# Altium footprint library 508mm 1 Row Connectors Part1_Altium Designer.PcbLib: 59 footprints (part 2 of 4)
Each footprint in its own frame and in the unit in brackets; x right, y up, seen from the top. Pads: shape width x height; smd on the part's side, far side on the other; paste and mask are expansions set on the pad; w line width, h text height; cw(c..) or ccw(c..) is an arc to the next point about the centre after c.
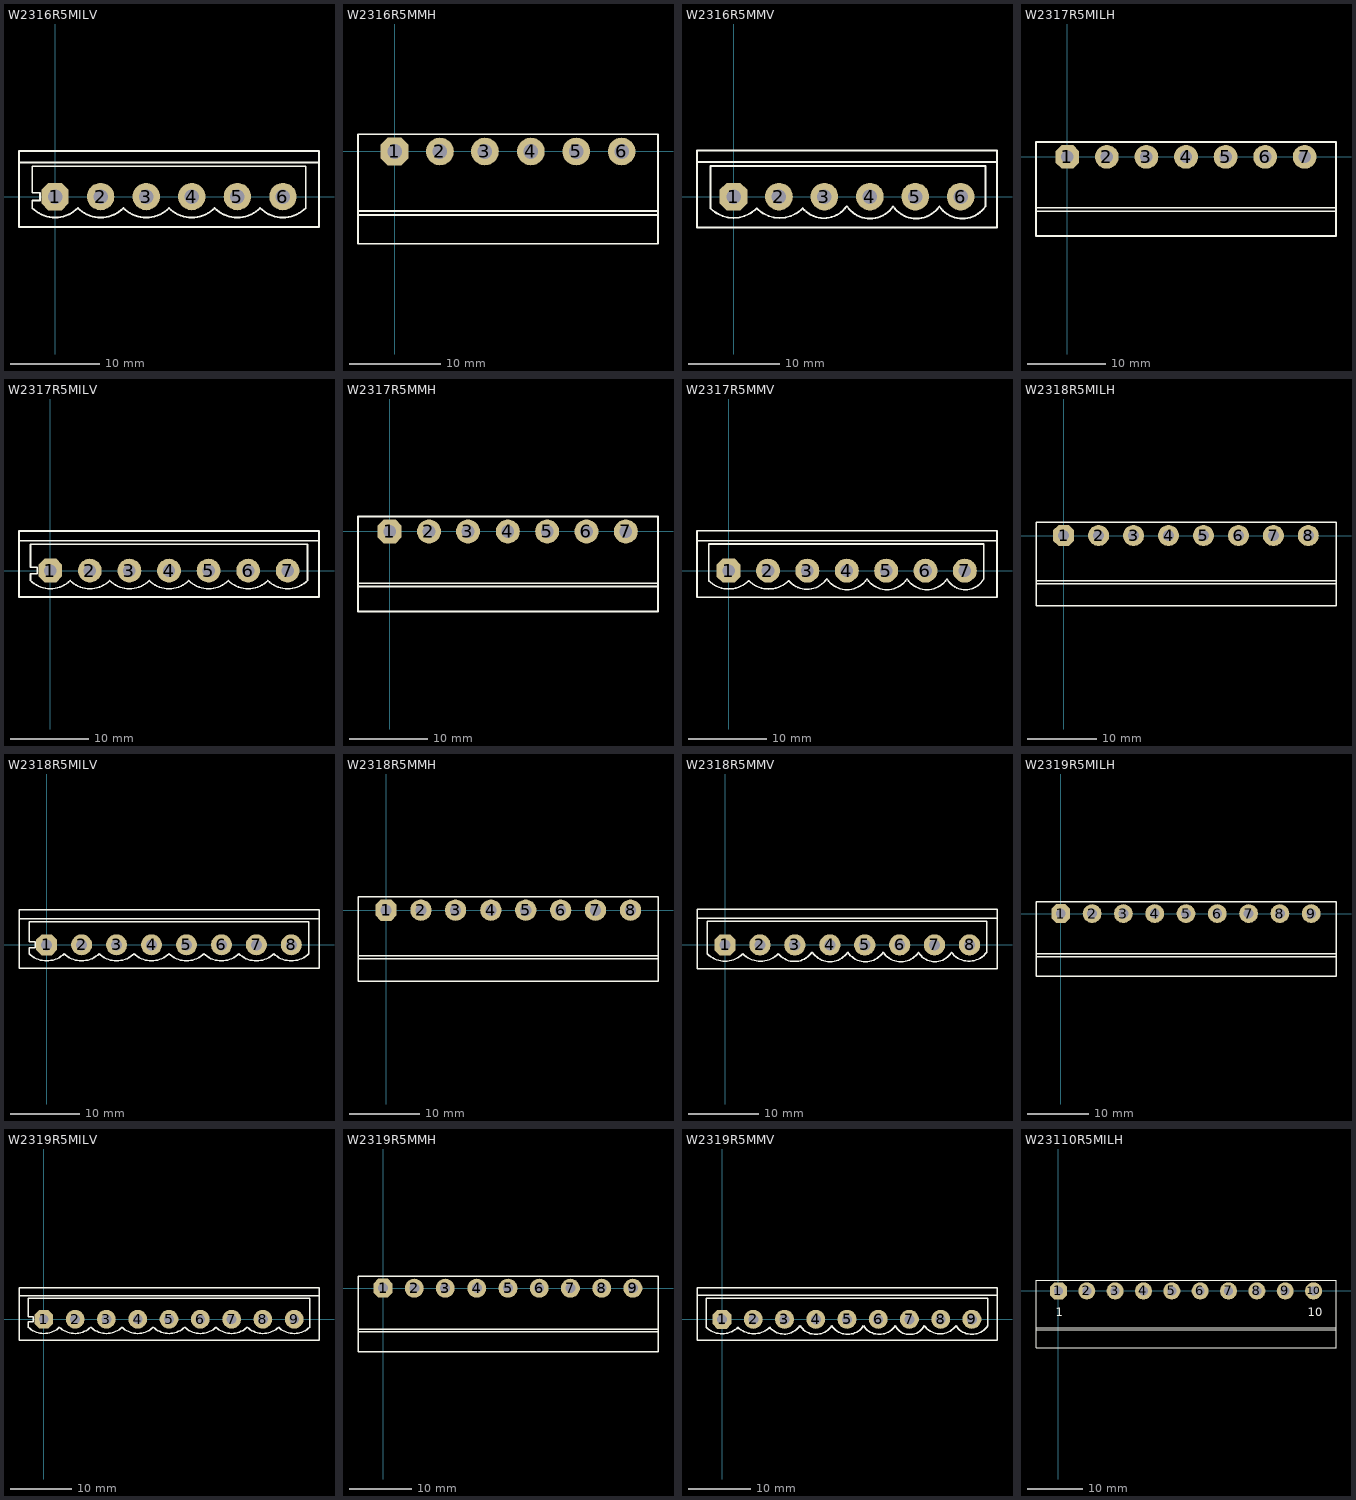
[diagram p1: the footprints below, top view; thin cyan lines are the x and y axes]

## W2316R5MILV [mil] "M.Hariri (Altium Designer)"
pads (6):
  oct 120x120 hole 62.99: 1(0,0)
  round 120 hole 62.99: 2(200,0) 3(400,0) 4(600,0) 5(800,0) 6(1000,0)
Top Overlay:
  lines w8: -158.33,150 1158.33,150 ; -100.17,-50.17 ccw(c0,50) 100.17,-50.17 ; -100,-50 -100,-16.67 -66.67,-16.67 -66.67,16.67 -100,16.67 -100,133.33 1100,133.33 1100,-50 ; 99.83,-50.17 ccw(c200,50) 300.17,-50.17 ; 299.83,-50.17 ccw(c400,50) 500.17,-50.17 ; 499.83,-50.17 ccw(c600,50) 700.17,-50.17 ; 699.83,-50.17 ccw(c800,50) 900.17,-50.17 ; 899.83,-50.17 ccw(c1000,50) 1100.17,-50.17 ; -158.33,-133.33 1158.33,-133.33 1158.33,200 -158.33,200 -158.33,-133.33

## W2316R5MMH [mil] "M.Hariri (Altium Designer)"
pads (6):
  oct 120x120 hole 62.99: 1(0,0)
  round 120 hole 62.99: 2(196.67,0) 3(391.67,0) 4(590.83,0) 5(787.5,0) 6(984.17,0)
Top Overlay:
  lines w8: -158.33,-275 1141.67,-275 ; -158.33,-258.33 1141.67,-258.33 ; -158.33,-400 -158.33,75 1141.67,75 1141.67,-400 -158.33,-400

## W2316R5MMV [mil] "M.Hariri (Altium Designer)"
pads (6):
  oct 120x120 hole 62.99: 1(0,0)
  round 120 hole 62.99: 2(196.67,0) 3(393.33,0) 4(590.83,0) 5(787.5,0) 6(984.17,0)
Top Overlay:
  lines w8: -158.33,150 1141.67,150 ; -100.17,-50.17 ccw(c0,50) 100.17,-50.17 ; -100,-50 -100,133.33 1091.67,133.33 1091.67,-41.67 ; 99.83,-50.17 ccw(c200,50) 300.17,-50.17 ; 299.7,-49.47 ccw(c391.67,25) 489.77,-41.17 ; 492.18,-42.1 ccw(c591.67,25) 691.15,-42.1 ; 692.18,-42.1 ccw(c791.67,25) 891.15,-42.1 ; 892.18,-42.1 ccw(c991.67,25) 1091.15,-42.1 ; -158.33,-133.33 1141.67,-133.33 1141.67,200 -158.33,200 -158.33,-133.33

## W2317R5MILH [mil] "M.Hariri (Altium Designer)"
pads (7):
  oct 120x120 hole 62.99: 1(0,0)
  round 120 hole 62.99: 2(200,0) 3(400,0) 4(600,0) 5(800,0) 6(1000,0) 7(1200,0)
Top Overlay:
  lines w8: -158.33,-275 1358.33,-275 ; -158.33,-258.33 1358.33,-258.33 ; -158.33,-400 -158.33,75 1358.33,75 1358.33,-400 -158.33,-400

## W2317R5MILV [mil] "M.Hariri (Altium Designer)"
pads (7):
  oct 120x120 hole 62.99: 1(0,0)
  round 120 hole 62.99: 2(200,0) 3(400,0) 4(600,0) 5(800,0) 6(1000,0) 7(1200,0)
Top Overlay:
  lines w8: -158.33,150 1358.33,150 ; -100.17,-50.17 ccw(c0,50) 100.17,-50.17 ; -100,-50 -100,-16.67 -66.67,-16.67 -66.67,16.67 -100,16.67 -100,133.33 1300,133.33 1300,-50 ; 99.83,-50.17 ccw(c200,50) 300.17,-50.17 ; 299.83,-50.17 ccw(c400,50) 500.17,-50.17 ; 499.83,-50.17 ccw(c600,50) 700.17,-50.17 ; 699.83,-50.17 ccw(c800,50) 900.17,-50.17 ; 899.83,-50.17 ccw(c1000,50) 1100.17,-50.17 ; 1099.83,-50.17 ccw(c1200,50) 1300.17,-50.17 ; -158.33,-133.33 1358.33,-133.33 1358.33,200 -158.33,200 -158.33,-133.33

## W2317R5MMH [mil] "M.Hariri (Altium Designer)"
pads (7):
  oct 120x120 hole 62.99: 1(0,0)
  round 120 hole 62.99: 2(196.67,0) 3(391.67,0) 4(590.83,0) 5(787.5,0) 6(984.17,0) 7(1180.83,0)
Top Overlay:
  lines w8: -158.33,-275 1341.67,-275 ; -158.33,-258.33 1341.67,-258.33 ; -158.33,-400 1341.67,-400 1341.67,75 -158.33,75 -158.33,-400

## W2317R5MMV [mil] "M.Hariri (Altium Designer)"
pads (7):
  oct 120x120 hole 62.99: 1(0,0)
  round 120 hole 62.99: 2(196.67,0) 3(393.33,0) 4(590.83,0) 5(787.5,0) 6(984.17,0) 7(1180.83,0)
Top Overlay:
  lines w8: -158.33,150 1341.67,150 ; -100.17,-50.17 ccw(c0,50) 100.17,-50.17 ; -100,-50 -100,133.33 1275,133.33 1275,-41.67 ; 99.83,-50.17 ccw(c200,50) 300.17,-50.17 ; 299.7,-49.47 ccw(c391.67,25) 489.77,-41.17 ; 492.18,-42.1 ccw(c591.67,25) 691.15,-42.1 ; 692.18,-42.1 ccw(c791.67,25) 891.15,-42.1 ; 892.18,-42.1 ccw(c991.67,25) 1091.15,-42.1 ; 1092.23,-42.17 ccw(c1183.33,8.33) 1274.44,-42.17 ; -158.33,-133.33 1341.67,-133.33 1341.67,200 -158.33,200 -158.33,-133.33

## W2318R5MILH [mil] "M.Hariri (Altium Designer)"
pads (8):
  oct 120x120 hole 62.99: 1(0,0)
  round 120 hole 62.99: 2(200,0) 3(400,0) 4(600,0) 5(800,0) 6(1000,0) 7(1200,0) 8(1400,0)
Top Overlay:
  lines w8: -158.33,-275 1558.33,-275 ; -158.33,-258.33 1558.33,-258.33 ; -158.33,-400 -158.33,75 1558.33,75 1558.33,-400 -158.33,-400

## W2318R5MILV [mil] "M.Hariri (Altium Designer)"
pads (8):
  oct 120x120 hole 62.99: 1(0,0)
  round 120 hole 62.99: 2(200,0) 3(400,0) 4(600,0) 5(800,0) 6(1000,0) 7(1200,0) 8(1400,0)
Top Overlay:
  lines w8: -158.33,150 1558.33,150 ; -100.17,-50.17 ccw(c0,50) 100.17,-50.17 ; -100,-50 -100,-16.67 -66.67,-16.67 -66.67,16.67 -100,16.67 -100,133.33 1500,133.33 1500,-50 ; 99.83,-50.17 ccw(c200,50) 300.17,-50.17 ; 299.83,-50.17 ccw(c400,50) 500.17,-50.17 ; 499.83,-50.17 ccw(c600,50) 700.17,-50.17 ; 699.83,-50.17 ccw(c800,50) 900.17,-50.17 ; 899.83,-50.17 ccw(c1000,50) 1100.17,-50.17 ; 1099.83,-50.17 ccw(c1200,50) 1300.17,-50.17 ; 1299.83,-50.17 ccw(c1400,50) 1500.17,-50.17 ; -158.33,-133.33 1558.33,-133.33 1558.33,200 -158.33,200 -158.33,-133.33

## W2318R5MMH [mil] "M.Hariri (Altium Designer)"
pads (8):
  oct 120x120 hole 62.99: 1(0,0)
  round 120 hole 62.99: 2(196.67,0) 3(391.67,0) 4(590.83,0) 5(787.5,0) 6(984.17,0) 7(1180.83,0) 8(1378.33,0)
Top Overlay:
  lines w8: -158.33,-275 1533.33,-275 ; -158.33,-258.33 1533.33,-258.33 ; -158.33,-400 -158.33,75 1533.33,75 1533.33,-400 -158.33,-400

## W2318R5MMV [mil] "M.Hariri (Altium Designer)"
pads (8):
  oct 120x120 hole 62.99: 1(0,0)
  round 120 hole 62.99: 2(196.67,0) 3(393.33,0) 4(590.83,0) 5(787.5,0) 6(984.17,0) 7(1180.83,0) 8(1378.33,0)
Top Overlay:
  lines w8: -158.33,150 1533.33,150 ; -100.17,-50.17 ccw(c0,50) 100.17,-50.17 ; -100,-50 -100,133.33 1475,133.33 1475,-41.67 ; 99.83,-50.17 ccw(c200,50) 300.17,-50.17 ; 299.7,-49.47 ccw(c391.67,25) 489.77,-41.17 ; 492.18,-42.1 ccw(c591.67,25) 691.15,-42.1 ; 692.18,-42.1 ccw(c791.67,25) 891.15,-42.1 ; 892.18,-42.1 ccw(c991.67,25) 1091.15,-42.1 ; 1092.23,-42.17 ccw(c1183.33,8.33) 1274.44,-42.17 ; 1275.17,-41.89 ccw(c1375,33.33) 1474.83,-41.89 ; -158.33,-133.33 1533.33,-133.33 1533.33,200 -158.33,200 -158.33,-133.33

## W2319R5MILH [mil] "M.Hariri (Altium Designer)"
pads (9):
  oct 120x120 hole 62.99: 1(0,0)
  round 120 hole 62.99: 2(200,0) 3(400,0) 4(600,0) 5(800,0) 6(1000,0) 7(1200,0) 8(1400,0) 9(1600,0)
Top Overlay:
  lines w8: -158.33,-275 1758.33,-275 ; -158.33,-258.33 1758.33,-258.33 ; -158.33,-400 1758.33,-400 1758.33,75 -158.33,75 -158.33,-400

## W2319R5MILV [mil] "M.Hariri (Altium Designer)"
pads (9):
  oct 120x120 hole 62.99: 1(0,0)
  round 120 hole 62.99: 2(200,0) 3(400,0) 4(600,0) 5(800,0) 6(1000,0) 7(1200,0) 8(1400,0) 9(1600,0)
Top Overlay:
  lines w8: -158.33,150 1758.33,150 ; -100.17,-50.17 ccw(c0,50) 100.17,-50.17 ; -100,-50 -100,-16.67 -66.67,-16.67 -66.67,16.67 -100,16.67 -100,133.33 1700,133.33 1700,-50 ; 99.83,-50.17 ccw(c200,50) 300.17,-50.17 ; 299.83,-50.17 ccw(c400,50) 500.17,-50.17 ; 499.83,-50.17 ccw(c600,50) 700.17,-50.17 ; 699.83,-50.17 ccw(c800,50) 900.17,-50.17 ; 899.83,-50.17 ccw(c1000,50) 1100.17,-50.17 ; 1099.83,-50.17 ccw(c1200,50) 1300.17,-50.17 ; 1299.83,-50.17 ccw(c1400,50) 1500.17,-50.17 ; 1499.83,-50.17 ccw(c1600,50) 1700.17,-50.17 ; -158.33,-133.33 1758.33,-133.33 1758.33,200 -158.33,200 -158.33,-133.33

## W2319R5MMH [mil] "M.Hariri (Altium Designer)"
pads (9):
  oct 120x120 hole 62.99: 1(0,0)
  round 120 hole 62.99: 2(196.67,0) 3(391.67,0) 4(590.83,0) 5(787.5,0) 6(984.17,0) 7(1180.83,0) 8(1378.33,0) 9(1575,0)
Top Overlay:
  lines w8: -158.33,-275 1733.33,-275 ; -158.33,-258.33 1733.33,-258.33 ; -158.33,-400 1733.33,-400 1733.33,75 -158.33,75 -158.33,-400

## W2319R5MMV [mil] "M.Hariri (Altium Designer)"
pads (9):
  oct 120x120 hole 62.99: 1(0,0)
  round 120 hole 62.99: 2(196.67,0) 3(393.33,0) 4(590.83,0) 5(787.5,0) 6(984.17,0) 7(1180.83,0) 8(1378.33,0) 9(1575,0)
Top Overlay:
  lines w8: -158.33,150 1733.33,150 ; -100.17,-50.17 ccw(c0,50) 100.17,-50.17 ; -100,-50 -100,133.33 1675,133.33 1675,-41.67 ; 99.83,-50.17 ccw(c200,50) 300.17,-50.17 ; 299.7,-49.47 ccw(c391.67,25) 489.77,-41.17 ; 492.18,-42.1 ccw(c591.67,25) 691.15,-42.1 ; 692.18,-42.1 ccw(c791.67,25) 891.15,-42.1 ; 892.18,-42.1 ccw(c991.67,25) 1091.15,-42.1 ; 1092.23,-42.17 ccw(c1183.33,8.33) 1274.44,-42.17 ; 1275.17,-41.89 ccw(c1375,33.33) 1474.83,-41.89 ; 1475.52,-42.1 ccw(c1575,25) 1674.48,-42.1 ; -158.33,-133.33 -158.33,200 1733.33,200 1733.33,-133.33 -158.33,-133.33

## W23110R5MILH [mil] "M.Hariri (Altium Designer)"
pads (10):
  oct 120x120 hole 62.99: 1(0,0)
  round 120 hole 62.99: 2(200,0) 3(400,0) 4(600,0) 5(800,0) 6(1000,0) 7(1200,0) 8(1400,0) 9(1600,0) 10(1800,0)
Top Overlay:
  lines w8: -158.33,-275 1958.33,-275 ; -158.33,-258.33 1958.33,-258.33 ; -158.33,-400 -158.33,75 1958.33,75 1958.33,-400 -158.33,-400
  text "1" at -20,-180 h60
  text "10" at 1760,-180 h60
